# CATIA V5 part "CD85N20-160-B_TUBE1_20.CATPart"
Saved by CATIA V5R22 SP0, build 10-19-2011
Part number: CD85N20-160-B_TUBE1_20
Revision: ANY
Definition: UNKNOWN
Nomenclature: CD85N20-160-B_TUBE1_20
Source: Unknown
Bounding box of the stored display mesh (mm): x -10.8 to 10.8, y -10.8 to 10.636, z -96 to 96
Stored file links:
  U:\S9A\PER\CAO\Assemblage\Reservoir_Boite\Verin\Test_Poussoir_2\Test\CD85N20-160-B_TUBE1_20.CATPart
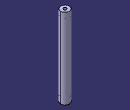
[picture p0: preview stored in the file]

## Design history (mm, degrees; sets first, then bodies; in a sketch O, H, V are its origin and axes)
Body1 "CHAMBER" (main body)
  Solid1: solid without history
